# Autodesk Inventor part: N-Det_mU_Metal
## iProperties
Shininess: 64.0
Length Units: 11269
Angle Units: 11279
Time Units: 11290
Mass Units: 11283
Length Display Precision: 3
Angle Display Precision: 2
Compacted: True
Part Number: N-Det_mU_Metal
Document SubType Name: Modeling
Created: 2005-04
Material: Steel, Mild
Designer: John Blackburn
Manufacturer: Standard
Standards Organization: Custom
Density: 0.0
Volumn: 0.0
Area: 0.0
PropertySet Name: Model Information
Control State: 0
Master: False
Checked Out: False
Author: John Blackburn
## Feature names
1. Extrusion1
